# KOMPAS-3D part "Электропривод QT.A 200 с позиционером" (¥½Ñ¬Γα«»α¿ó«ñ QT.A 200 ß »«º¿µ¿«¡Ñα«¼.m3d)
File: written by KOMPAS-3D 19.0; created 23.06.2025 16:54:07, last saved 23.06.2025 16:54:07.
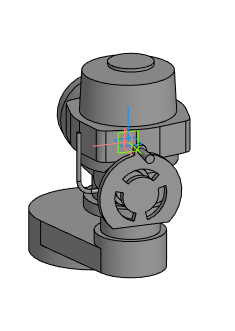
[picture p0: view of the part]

Document properties: Автор: Евгений; Полное имя файла: E:\Dendor Работа Сачек\3D для проектировщиков\3.5 Тип QT.А Электропривод\stp_Электропривод QT.A с позиционером\Электропривод QT.A 200 с позиционером.m3d

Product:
- Part/product: Электропривод QT.A 200 с позиционером

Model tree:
1. Операция без истории:1  (labels: Электропривод QT.A 200 с позиционером)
